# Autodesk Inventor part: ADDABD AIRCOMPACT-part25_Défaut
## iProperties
Shininess: 64.0
Length Units: 11269
Angle Units: 11279
Time Units: 11290
Mass Units: 11283
Length Display Precision: 3
Angle Display Precision: 2
Compacted: True
Part Number: ADDABD AIRCOMPACT-part25_Défaut
Document SubType Name: Modeling
Created: 2006-01
Material: Par défaut
Designer: riri
Density: 0.0
Volumn: 0.0
Area: 0.0
PropertySet Name: Model Information
Control State: 0
Master: False
Checked Out: False
Author: riri
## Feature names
1. Base1
